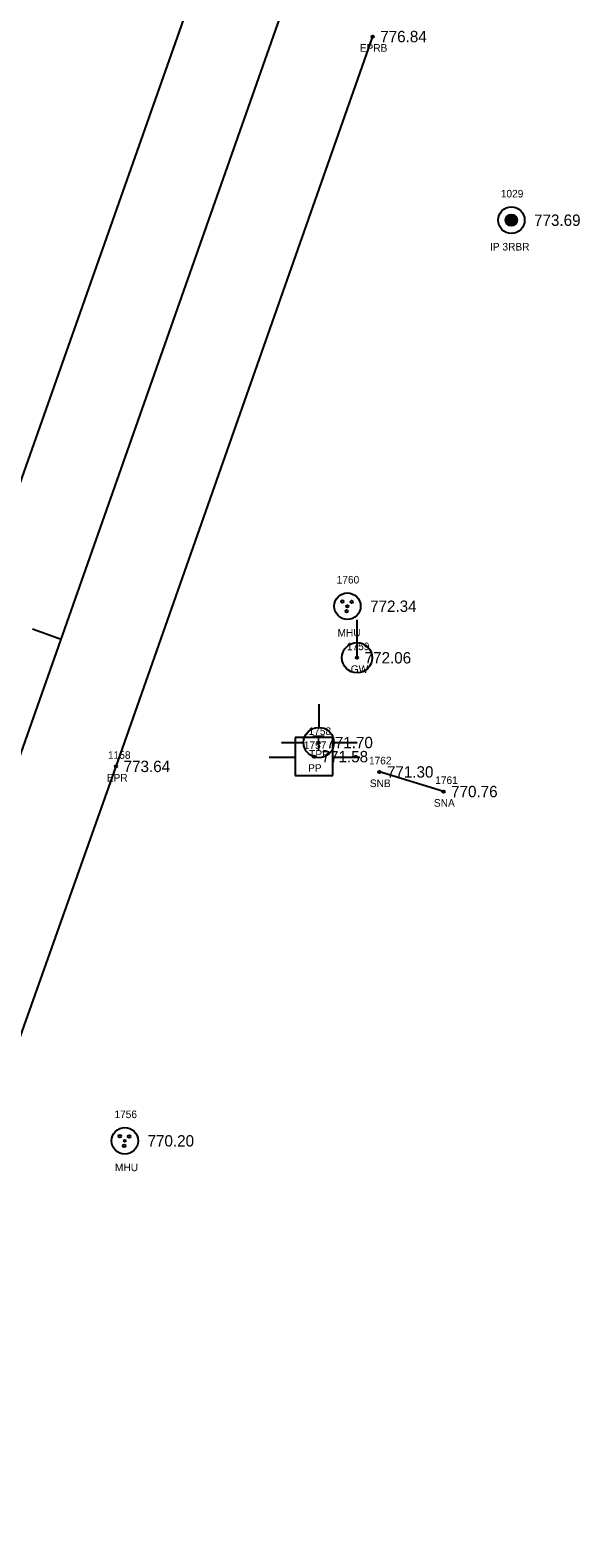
# Model space of a CAD drawing. Extents: x 1736563 to 1738032, y 1150548 to 1154248.
# Drawn here: x 1737901.6 to 1737974.2, y 1153946.3 to 1154145.2 of the extents above; entities that cross this region are included whole.
import ezdxf

# ---------------------------------------------------------------- set-up
doc = ezdxf.new("R2010")
doc.units = 0
for name, color, linetype in [('RD_EX_BldgApp', 7, 'Continuous'), ('RD_EX_BldgApp_txCode', 7, 'Continuous'), ('RD_EX_DR_Inlet', 7, 'Continuous'), ('RD_EX_DV_Prop_txCode', 7, 'Continuous'), ('RD_EX_DV_PropPin', 7, 'Continuous'), ('RD_EX_Road', 7, 'Continuous'), ('RD_EX_Road_txCode', 7, 'Continuous'), ('RD_EX_TX_BldgApp_ELEV', 7, 'Continuous'), ('RD_EX_TX_DV_Prop_ELEV', 7, 'Continuous'), ('RD_EX_TX_Road_ELEV', 7, 'Continuous'), ('RD_EX_TX_UT_ELEV', 7, 'Continuous'), ('RD_EX_UT', 7, 'Continuous'), ('RD_EX_UT_txCode', 7, 'Continuous'), ('RD_HC_Cl', 7, 'Continuous'), ('RD_HC_Data_Tic', 7, 'Continuous'), ('RD_HC_Survey_ELEV', 7, 'Continuous'), ('RD_SMD_Locator', 7, 'Continuous')]:
    doc.layers.add(name, color=color, linetype=linetype)

msp = doc.modelspace()

# ---------------------------------------------------------------- linework, layer by layer
at = {"layer": 'RD_EX_BldgApp'}
msp.add_line((1737956.17, 1154044.75), (1737947.7, 1154047.34), dxfattribs=at)
at = {"layer": 'RD_EX_DR_Inlet'}
for centre, radius in [((1737943.48, 1154069.21), 1.75), ((1737942.81, 1154069.84), 0.175), ((1737943.39, 1154068.54), 0.175), ((1737944.04, 1154069.77), 0.175), ((1737914.11, 1153998.65), 1.75), ((1737913.45, 1153999.28), 0.175), ((1737914.67, 1153999.21), 0.175), ((1737914.03, 1153997.99), 0.175)]:
    msp.add_circle(centre, radius, dxfattribs=at)
at = {"layer": 'RD_EX_DV_PropPin'}
for p, q in [((1737964.38, 1154119.97), (1737964.38, 1154120.36)), ((1737964.42, 1154119.87), (1737964.42, 1154120.46)), ((1737964.45, 1154119.8), (1737964.45, 1154120.53)), ((1737964.49, 1154119.74), (1737964.49, 1154120.59)), ((1737964.52, 1154119.69), (1737964.52, 1154120.64)), ((1737964.56, 1154119.65), (1737964.56, 1154120.68)), ((1737964.59, 1154119.61), (1737964.59, 1154120.72)), ((1737964.63, 1154119.58), (1737964.63, 1154120.75)), ((1737964.66, 1154119.55), (1737964.66, 1154120.77)), ((1737964.7, 1154119.53), (1737964.7, 1154120.8)), ((1737964.73, 1154119.51), (1737964.73, 1154120.82)), ((1737964.77, 1154119.49), (1737964.77, 1154120.84)), ((1737964.8, 1154119.47), (1737964.8, 1154120.86)), ((1737964.84, 1154119.46), (1737964.84, 1154120.87)), ((1737964.87, 1154119.44), (1737964.87, 1154120.89)), ((1737964.91, 1154119.43), (1737964.91, 1154120.9)), ((1737964.94, 1154119.42), (1737964.94, 1154120.91)), ((1737964.98, 1154119.42), (1737964.98, 1154120.91)), ((1737965.01, 1154119.41), (1737965.01, 1154120.92)), ((1737965.05, 1154119.41), (1737965.05, 1154120.92)), ((1737965.08, 1154119.4), (1737965.08, 1154120.92)), ((1737965.12, 1154119.4), (1737965.12, 1154120.93)), ((1737965.15, 1154119.4), (1737965.15, 1154120.92)), ((1737965.19, 1154119.41), (1737965.19, 1154120.92)), ((1737965.22, 1154119.41), (1737965.22, 1154120.92)), ((1737965.26, 1154119.42), (1737965.26, 1154120.91)), ((1737965.29, 1154119.42), (1737965.29, 1154120.91)), ((1737965.33, 1154119.43), (1737965.33, 1154120.9)), ((1737965.36, 1154119.44), (1737965.36, 1154120.89)), ((1737965.4, 1154119.46), (1737965.4, 1154120.87)), ((1737965.43, 1154119.47), (1737965.43, 1154120.86)), ((1737965.47, 1154119.49), (1737965.47, 1154120.84)), ((1737965.5, 1154119.51), (1737965.5, 1154120.82)), ((1737965.54, 1154119.53), (1737965.54, 1154120.8)), ((1737965.57, 1154119.55), (1737965.57, 1154120.77)), ((1737965.61, 1154119.58), (1737965.61, 1154120.75)), ((1737965.64, 1154119.61), (1737965.64, 1154120.72)), ((1737965.68, 1154119.65), (1737965.68, 1154120.68)), ((1737965.71, 1154119.69), (1737965.71, 1154120.64)), ((1737965.75, 1154119.74), (1737965.75, 1154120.59)), ((1737965.78, 1154119.8), (1737965.78, 1154120.53)), ((1737965.82, 1154119.87), (1737965.82, 1154120.46)), ((1737965.85, 1154119.97), (1737965.85, 1154120.36))]:
    msp.add_line(p, q, dxfattribs=at)
for radius in [1.75, 0.761]:
    msp.add_circle((1737965.12, 1154120.16), radius, dxfattribs=at)
at = {"layer": 'RD_EX_Road'}
for points in [[(1737496.36, 1152940.55), (1737529.37, 1153032.75), (1737537.93, 1153057.4), (1737549.32, 1153089.17), (1737563.01, 1153127.73), (1737595.49, 1153219.95), (1737628.15, 1153312.67), (1737660.2, 1153403.8), (1737692.32, 1153495.67), (1737724.61, 1153587.75), (1737756.73, 1153679.29), (1737770.32, 1153718.5), (1737778.01, 1153740.46), (1737788.96, 1153772.48), (1737822.56, 1153867.79), (1737856.1, 1153962.19), (1737875.63, 1154016.18), (1737880.55, 1154030.08), (1737889.82, 1154055.89), (1737923.73, 1154151.97)], [(1737767.23, 1153635.63), (1737779.62, 1153670.7), (1737786.15, 1153689.96), (1737811.86, 1153764.64), (1737841.92, 1153849.66), (1737845.41, 1153858.54), (1737858.39, 1153893.35), (1737872.4, 1153934.23), (1737879.38, 1153953.57), (1737912.95, 1154048.07), (1737946.82, 1154144.4)]]:
    msp.add_lwpolyline(points, dxfattribs=at)
at = {"layer": 'RD_EX_UT'}
for p, q in [((1737944.76, 1154062.41), (1737944.76, 1154067.41)), ((1737939.71, 1154056.29), (1737939.71, 1154053.22)), ((1737934.78, 1154051.23), (1737937.71, 1154051.23)), ((1737941.57, 1154051.87), (1737936.57, 1154051.87)), ((1737936.57, 1154051.87), (1737936.57, 1154046.87)), ((1737941.57, 1154046.87), (1737941.57, 1154051.87)), ((1737941.71, 1154051.23), (1737944.78, 1154051.23)), ((1737933.14, 1154049.31), (1737936.61, 1154049.31)), ((1737941.5, 1154049.31), (1737945.14, 1154049.31)), ((1737936.57, 1154046.87), (1737941.57, 1154046.87))]:
    msp.add_line(p, q, dxfattribs=at)
for centre in [(1737944.76, 1154062.41), (1737939.71, 1154051.22)]:
    msp.add_circle(centre, 2, dxfattribs=at)
at = {"layer": 'RD_HC_Cl'}
msp.add_line((1736879.96, 1151154.46), (1737935.1, 1154148.31), dxfattribs=at)
at = {"layer": 'RD_HC_Data_Tic'}
msp.add_line((1737905.69, 1154064.84), (1737901.91, 1154066.17), dxfattribs=at)
at = {"layer": 'RD_SMD_Locator'}
for centre in [(1737946.82, 1154144.4), (1737965.12, 1154120.16), (1737943.48, 1154069.21), (1737944.76, 1154062.41), (1737939.71, 1154051.22), (1737939.08, 1154049.36), (1737912.95, 1154048.07), (1737947.7, 1154047.34), (1737956.17, 1154044.75), (1737914.11, 1153998.65)]:
    msp.add_circle(centre, 0.15, dxfattribs=at)

# ---------------------------------------------------------------- texts
at = {"layer": 'RD_EX_BldgApp_txCode'}
for s, p in [('1762', (1737946.33, 1154048.34)), ('1761', (1737955.08, 1154045.75)), ('SNB', (1737946.45, 1154045.34)), ('SNA', (1737954.9, 1154042.75))]:
    msp.add_text(s, height=1, dxfattribs=at).set_placement(p)
at = {"layer": 'RD_EX_DV_Prop_txCode'}
for s, p in [('1029', (1737963.73, 1154123.16)), ('IP 3RBR', (1737962.31, 1154116.16))]:
    msp.add_text(s, height=1, dxfattribs=at).set_placement(p)
at = {"layer": 'RD_EX_Road_txCode'}
for s, p in [('EPRB', (1737945.12, 1154142.4)), ('1158', (1737911.89, 1154049.07)), ('EPR', (1737911.73, 1154046.07))]:
    msp.add_text(s, height=1, dxfattribs=at).set_placement(p)
at = {"layer": 'RD_EX_TX_BldgApp_ELEV'}
for s, p in [('771.30', (1737948.7, 1154046.59)), ('770.76', (1737957.17, 1154044))]:
    msp.add_text(s, height=1.5, dxfattribs=at).set_placement(p)
at = {"layer": 'RD_EX_TX_DV_Prop_ELEV'}
msp.add_text('773.69', height=1.5, dxfattribs=at).set_placement((1737968.12, 1154119.41))
at = {"layer": 'RD_EX_TX_Road_ELEV'}
for s, p in [('776.84', (1737947.82, 1154143.65)), ('773.64', (1737913.95, 1154047.32))]:
    msp.add_text(s, height=1.5, dxfattribs=at).set_placement(p)
at = {"layer": 'RD_EX_TX_UT_ELEV'}
for s, p in [('772.34', (1737946.48, 1154068.46)), ('772.06', (1737945.76, 1154061.66)), ('771.70', (1737940.71, 1154050.47)), ('770.20', (1737917.11, 1153997.9))]:
    msp.add_text(s, height=1.5, dxfattribs=at).set_placement(p)
at = {"layer": 'RD_EX_UT'}
msp.add_text('T', height=2, dxfattribs=at).set_placement((1737938.86, 1154050.17))
at = {"layer": 'RD_EX_UT_txCode'}
for s, p in [('1760', (1737942.07, 1154072.21)), ('MHU', (1737942.18, 1154065.21)), ('1759', (1737943.41, 1154063.41)), ('GW', (1737943.92, 1154060.41)), ('1758', (1737938.36, 1154052.22)), ('1757', (1737937.73, 1154050.36)), ('TPP', (1737938.44, 1154049.22)), ('PP', (1737938.3, 1154047.36)), ('1756', (1737912.74, 1154001.65)), ('MHU', (1737912.81, 1153994.65))]:
    msp.add_text(s, height=1, dxfattribs=at).set_placement(p)
at = {"layer": 'RD_HC_Survey_ELEV'}
msp.add_text('771.58', height=1.5, dxfattribs=at).set_placement((1737940.08, 1154048.61))

doc.saveas('drawing.dxf')
